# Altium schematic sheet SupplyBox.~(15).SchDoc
size C; SheetNumber: 1; SheetTotal: 1
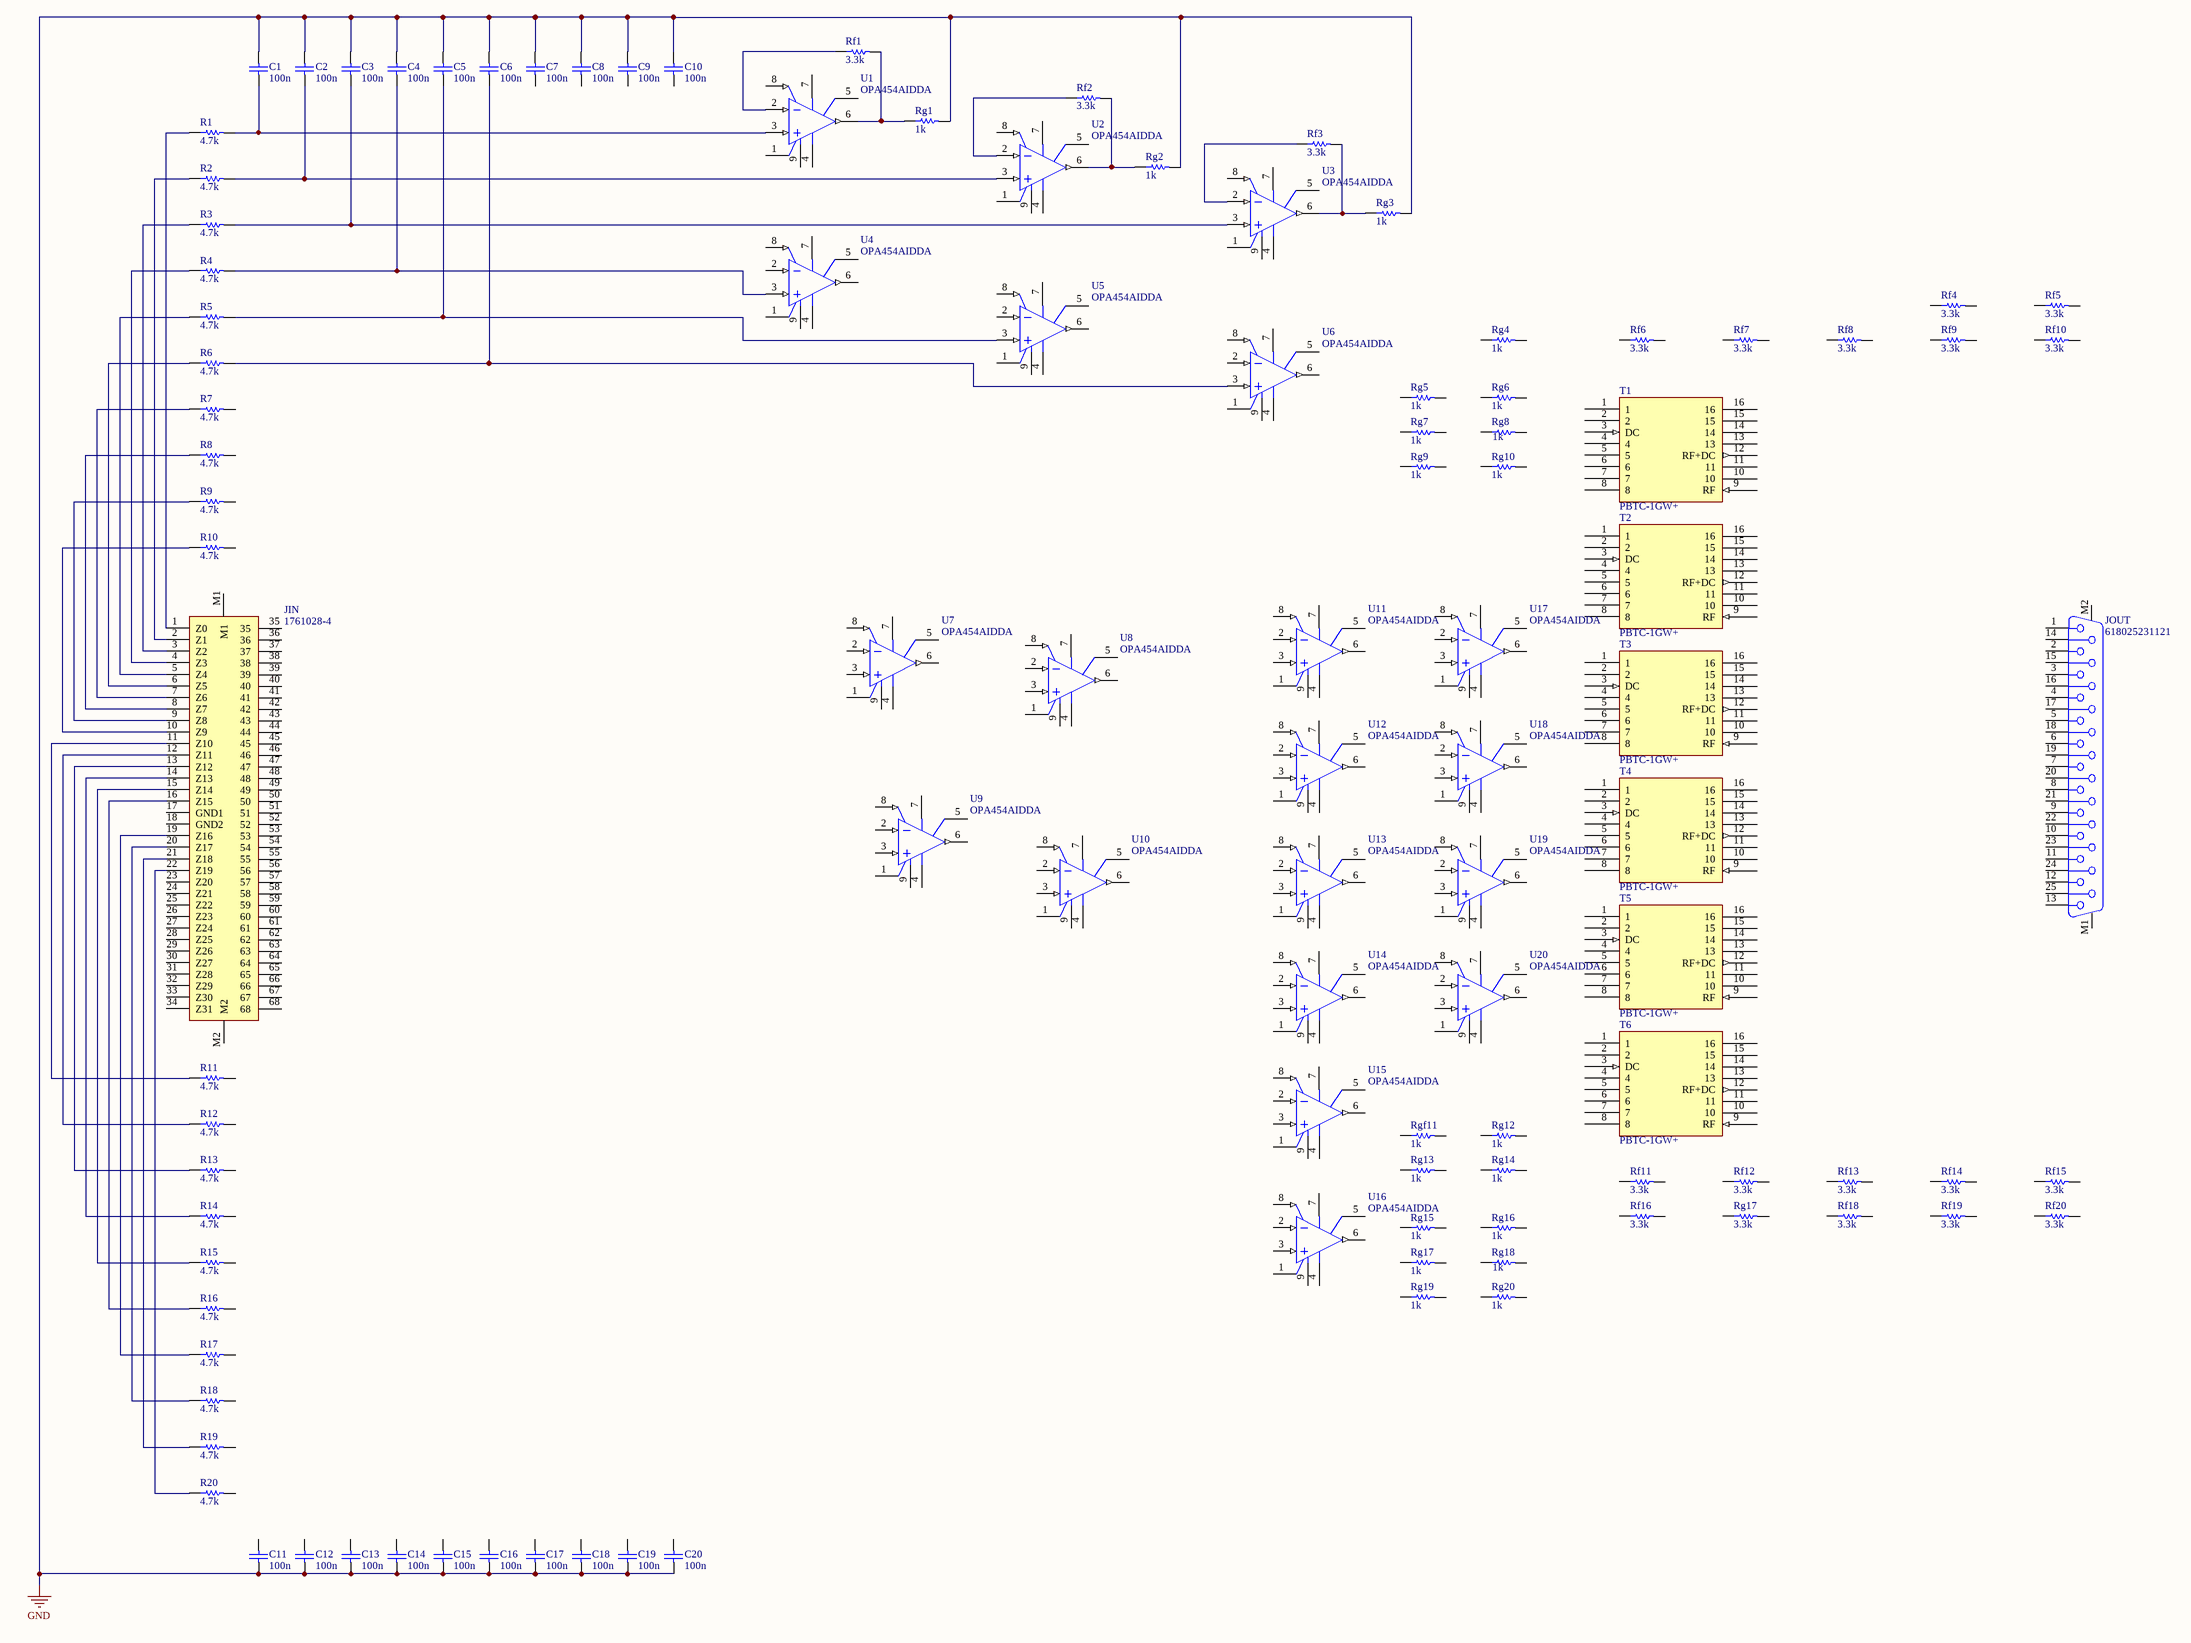
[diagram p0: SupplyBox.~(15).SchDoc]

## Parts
(Parts that share a designator on the sheet are numbered #1, #2 ... from top to bottom, then left to right.)
C1  100n  [CAPC2013X145X48NL20T23]
C2  100n  [CAPC2013X145X48NL20T23]
C3  100n  [CAPC2013X145X48NL20T23]
C4  100n  [CAPC2013X145X48NL20T23]
C5  100n  [CAPC2013X145X48NL20T23]
C6  100n  [CAPC2013X145X48NL20T23]
C7  100n  [CAPC2013X145X48NL20T23]
C8  100n  [CAPC2013X145X48NL20T23]
C9  100n  [CAPC2013X145X48NL20T23]
C10  100n  [CAPC2013X145X48NL20T23]
C11  100n  [CAPC2013X145X48NL20T23]
C12  100n  [CAPC2013X145X48NL20T23]
C13  100n  [CAPC2013X145X48NL20T23]
C14  100n  [CAPC2013X145X48NL20T23]
C15  100n  [CAPC2013X145X48NL20T23]
C16  100n  [CAPC2013X145X48NL20T23]
C17  100n  [CAPC2013X145X48NL20T23]
C18  100n  [CAPC2013X145X48NL20T23]
C19  100n  [CAPC2013X145X48NL20T23]
C20  100n  [CAPC2013X145X48NL20T23]
JIN  1761028-4  [1761028-4-Footprint-1]
JOUT  618025231121  [618025231121]
R1  4.7k  [RESC2013X60X35NL10T20]
R2  4.7k  [RESC2013X60X35NL10T20]
R3  4.7k  [RESC2013X60X35NL10T20]
R4  4.7k  [RESC2013X60X35NL10T20]
R5  4.7k  [RESC2013X60X35NL10T20]
R6  4.7k  [RESC2013X60X35NL10T20]
R7  4.7k  [RESC2013X60X35NL10T20]
R8  4.7k  [RESC2013X60X35NL10T20]
R9  4.7k  [RESC2013X60X35NL10T20]
R10  4.7k  [RESC2013X60X35NL10T20]
R11  4.7k  [RESC2013X60X35NL10T20]
R12  4.7k  [RESC2013X60X35NL10T20]
R13  4.7k  [RESC2013X60X35NL10T20]
R14  4.7k  [RESC2013X60X35NL10T20]
R15  4.7k  [RESC2013X60X35NL10T20]
R16  4.7k  [RESC2013X60X35NL10T20]
R17  4.7k  [RESC2013X60X35NL10T20]
R18  4.7k  [RESC2013X60X35NL10T20]
R19  4.7k  [RESC2013X60X35NL10T20]
R20  4.7k  [RESC2013X60X35NL10T20]
Rf1  3.3k  [RESC2013X60X35ML10T20]
Rf2  3.3k  [RESC2013X60X35ML10T20]
Rf3  3.3k  [RESC2013X60X35ML10T20]
Rf4  3.3k  [RESC2013X60X35ML10T20]
Rf5  3.3k  [RESC2013X60X35ML10T20]
Rf6  3.3k  [RESC2013X60X35ML10T20]
Rf7  3.3k  [RESC2013X60X35ML10T20]
Rf8  3.3k  [RESC2013X60X35ML10T20]
Rf9  3.3k  [RESC2013X60X35ML10T20]
Rf10  3.3k  [RESC2013X60X35ML10T20]
Rf11  3.3k  [RESC2013X60X35ML10T20]
Rf12  3.3k  [RESC2013X60X35ML10T20]
Rf13  3.3k  [RESC2013X60X35ML10T20]
Rf14  3.3k  [RESC2013X60X35ML10T20]
Rf15  3.3k  [RESC2013X60X35ML10T20]
Rf16  3.3k  [RESC2013X60X35ML10T20]
Rf18  3.3k  [RESC2013X60X35ML10T20]
Rf19  3.3k  [RESC2013X60X35ML10T20]
Rf20  3.3k  [RESC2013X60X35ML10T20]
Rg1  1k  [RESC2013X60X35ML10T20]
Rg2  1k  [RESC2013X60X35ML10T20]
Rg3  1k  [RESC2013X60X35ML10T20]
Rg4  1k  [RESC2013X60X35ML10T20]
Rg5  1k  [RESC2013X60X35ML10T20]
Rg6  1k  [RESC2013X60X35ML10T20]
Rg7  1k  [RESC2013X60X35ML10T20]
Rg8  1k  [RESC2013X60X35ML10T20]
Rg9  1k  [RESC2013X60X35ML10T20]
Rg10  1k  [RESC2013X60X35ML10T20]
Rg12  1k  [RESC2013X60X35ML10T20]
Rg13  1k  [RESC2013X60X35ML10T20]
Rg14  1k  [RESC2013X60X35ML10T20]
Rg15  1k  [RESC2013X60X35ML10T20]
Rg16  1k  [RESC2013X60X35ML10T20]
Rg17#1  3.3k  [RESC2013X60X35ML10T20]
Rg17#2  1k  [RESC2013X60X35ML10T20]
Rg18  1k  [RESC2013X60X35ML10T20]
Rg19  1k  [RESC2013X60X35ML10T20]
Rg20  1k  [RESC2013X60X35ML10T20]
Rgf11  1k  [RESC2013X60X35ML10T20]
T1  PBTC-1GW+  [PBTC-1GW+]
T2  PBTC-1GW+  [PBTC-1GW+]
T3  PBTC-1GW+  [PBTC-1GW+]
T4  PBTC-1GW+  [PBTC-1GW+]
T5  PBTC-1GW+  [PBTC-1GW+]
T6  PBTC-1GW+  [PBTC-1GW+]
U1  OPA454AIDDA  [DDA0008C_L]
U2  OPA454AIDDA  [DDA0008C_L]
U3  OPA454AIDDA  [DDA0008C_L]
U4  OPA454AIDDA  [DDA0008C_L]
U5  OPA454AIDDA  [DDA0008C_L]
U6  OPA454AIDDA  [DDA0008C_L]
U7  OPA454AIDDA  [DDA0008C_L]
U8  OPA454AIDDA  [DDA0008C_L]
U9  OPA454AIDDA  [DDA0008C_L]
U10  OPA454AIDDA  [DDA0008C_L]
U11  OPA454AIDDA  [DDA0008C_L]
U12  OPA454AIDDA  [DDA0008C_L]
U13  OPA454AIDDA  [DDA0008C_L]
U14  OPA454AIDDA  [DDA0008C_L]
U15  OPA454AIDDA  [DDA0008C_L]
U16  OPA454AIDDA  [DDA0008C_L]
U17  OPA454AIDDA  [DDA0008C_L]
U18  OPA454AIDDA  [DDA0008C_L]
U19  OPA454AIDDA  [DDA0008C_L]
U20  OPA454AIDDA  [DDA0008C_L]

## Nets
GND: C1.2 C2.2 C3.2 C4.2 C5.2 C6.2 C7.2 C8.2 C9.2 C10.2 C11.1 C12.1 C13.1 C14.1 C15.1 C16.1 C17.1 C18.1 C19.1 C20.1 Rg1.2 Rg2.2 Rg3.2
NetC1_1: C1.1 R1.2 U1.3(IN+)
NetC2_1: C2.1 R2.2 U2.3(IN+)
NetC3_1: C3.1 R3.2 U3.3(IN+)
NetC4_1: C4.1 R4.2 U4.3(IN+)
NetC5_1: C5.1 R5.2 U5.3(IN+)
NetC6_1: C6.1 R6.2 U6.3(IN+)
NetJIN_1: JIN.1(Z0) R1.1
NetJIN_2: JIN.2(Z1) R2.1
NetJIN_3: JIN.3(Z2) R3.1
NetJIN_4: JIN.4(Z3) R4.1
NetJIN_5: JIN.5(Z4) R5.1
NetJIN_6: JIN.6(Z5) R6.1
NetJIN_7: JIN.7(Z6) R7.1
NetJIN_8: JIN.8(Z7) R8.1
NetJIN_9: JIN.9(Z8) R9.1
NetJIN_10: JIN.10(Z9) R10.1
NetJIN_11: JIN.11(Z10) R11.1
NetJIN_12: JIN.12(Z11) R12.1
NetJIN_13: JIN.13(Z12) R13.1
NetJIN_14: JIN.14(Z13) R14.1
NetJIN_15: JIN.15(Z14) R15.1
NetJIN_16: JIN.16(Z15) R16.1
NetJIN_19: JIN.19(Z16) R17.1
NetJIN_20: JIN.20(Z17) R18.1
NetJIN_21: JIN.21(Z18) R19.1
NetJIN_22: JIN.22(Z19) R20.1
NetRf1_1: Rf1.1 U1.2(IN-)
NetRf1_2: Rf1.2 Rg1.1 U1.6(OUT)
NetRf2_1: Rf2.1 U2.2(IN-)
NetRf2_2: Rf2.2 Rg2.1 U2.6(OUT)
NetRf3_1: Rf3.1 U3.2(IN-)
NetRf3_2: Rf3.2 Rg3.1 U3.6(OUT)

Not connected (* = marked no-connect by the designer): C7 1; C8 1; C9 1; C10 1; C11 2; C12 2; C13 2; C14 2; C15 2; C16 2; C17 2; C18 2; C19 2; C20 2; JIN 17(GND1) 18(GND2) 23(Z20) 24(Z21) 25(Z22) 26(Z23) 27(Z24) 28(Z25) 29(Z26) 30(Z27) 31(Z28) 32(Z29) 33(Z30) 34(Z31) 35 36 37 38 39 40 41 42 43 44 45 46 47 48 49 50 51 52 53 54 55 56 57 58 59 60 61 62 63 64 65 66 67 68 M1 M2; JOUT 1 2 3 4 5 6 7 8 9 10 11 12 13 14 15 16 17 18 19 20 21 22 23 24 25 M1 M2; R7 2; R8 2; R9 2; R10 2; R11 2; R12 2; R13 2; R14 2; R15 2; R16 2; R17 2; R18 2; R19 2; R20 2; Rf4 1 2; Rf5 1 2; Rf6 1 2; Rf7 1 2; Rf8 1 2; Rf9 1 2; Rf10 1 2; Rf11 1 2; Rf12 1 2; Rf13 1 2; Rf14 1 2; Rf15 1 2; Rf16 1 2; Rf18 1 2; Rf19 1 2; Rf20 1 2; Rg4 1 2; Rg5 1 2; Rg6 1 2; Rg7 1 2; Rg8 1 2; Rg9 1 2; Rg10 1 2; Rg12 1 2; Rg13 1 2; Rg14 1 2; Rg15 1 2; Rg16 1 2; Rg17#1 1 2; Rg17#2 1 2; Rg18 1 2; Rg19 1 2; Rg20 1 2; Rgf11 1 2; T1 1 2 3(DC) 4 5 6 7 8 9(RF) 10 11 12(RF+DC) 13 14 15 16; T2 1 2 3(DC) 4 5 6 7 8 9(RF) 10 11 12(RF+DC) 13 14 15 16; T3 1 2 3(DC) 4 5 6 7 8 9(RF) 10 11 12(RF+DC) 13 14 15 16; T4 1 2 3(DC) 4 5 6 7 8 9(RF) 10 11 12(RF+DC) 13 14 15 16; T5 1 2 3(DC) 4 5 6 7 8 9(RF) 10 11 12(RF+DC) 13 14 15 16; T6 1 2 3(DC) 4 5 6 7 8 9(RF) 10 11 12(RF+DC) 13 14 15 16; U1 1(E/D_COM) 4(V-) 5(STATUS_FLAG) 7(V+) 8(E/D) 9(EP); U2 1(E/D_COM) 4(V-) 5(STATUS_FLAG) 7(V+) 8(E/D) 9(EP); U3 1(E/D_COM) 4(V-) 5(STATUS_FLAG) 7(V+) 8(E/D) 9(EP); U4 1(E/D_COM) 2(IN-) 4(V-) 5(STATUS_FLAG) 6(OUT) 7(V+) 8(E/D) 9(EP); U5 1(E/D_COM) 2(IN-) 4(V-) 5(STATUS_FLAG) 6(OUT) 7(V+) 8(E/D) 9(EP); U6 1(E/D_COM) 2(IN-) 4(V-) 5(STATUS_FLAG) 6(OUT) 7(V+) 8(E/D) 9(EP); U7 1(E/D_COM) 2(IN-) 3(IN+) 4(V-) 5(STATUS_FLAG) 6(OUT) 7(V+) 8(E/D) 9(EP); U8 1(E/D_COM) 2(IN-) 3(IN+) 4(V-) 5(STATUS_FLAG) 6(OUT) 7(V+) 8(E/D) 9(EP); U9 1(E/D_COM) 2(IN-) 3(IN+) 4(V-) 5(STATUS_FLAG) 6(OUT) 7(V+) 8(E/D) 9(EP); U10 1(E/D_COM) 2(IN-) 3(IN+) 4(V-) 5(STATUS_FLAG) 6(OUT) 7(V+) 8(E/D) 9(EP); U11 1(E/D_COM) 2(IN-) 3(IN+) 4(V-) 5(STATUS_FLAG) 6(OUT) 7(V+) 8(E/D) 9(EP); U12 1(E/D_COM) 2(IN-) 3(IN+) 4(V-) 5(STATUS_FLAG) 6(OUT) 7(V+) 8(E/D) 9(EP); U13 1(E/D_COM) 2(IN-) 3(IN+) 4(V-) 5(STATUS_FLAG) 6(OUT) 7(V+) 8(E/D) 9(EP); U14 1(E/D_COM) 2(IN-) 3(IN+) 4(V-) 5(STATUS_FLAG) 6(OUT) 7(V+) 8(E/D) 9(EP); U15 1(E/D_COM) 2(IN-) 3(IN+) 4(V-) 5(STATUS_FLAG) 6(OUT) 7(V+) 8(E/D) 9(EP); U16 1(E/D_COM) 2(IN-) 3(IN+) 4(V-) 5(STATUS_FLAG) 6(OUT) 7(V+) 8(E/D) 9(EP); U17 1(E/D_COM) 2(IN-) 3(IN+) 4(V-) 5(STATUS_FLAG) 6(OUT) 7(V+) 8(E/D) 9(EP); U18 1(E/D_COM) 2(IN-) 3(IN+) 4(V-) 5(STATUS_FLAG) 6(OUT) 7(V+) 8(E/D) 9(EP); U19 1(E/D_COM) 2(IN-) 3(IN+) 4(V-) 5(STATUS_FLAG) 6(OUT) 7(V+) 8(E/D) 9(EP); U20 1(E/D_COM) 2(IN-) 3(IN+) 4(V-) 5(STATUS_FLAG) 6(OUT) 7(V+) 8(E/D) 9(EP)

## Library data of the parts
C1-C20 = CMP-2007-03167-1: Manufacturer: Vitramon; Part Number: VJ0805Y104KNAAT
JIN = CMP-002-00071-1: Telecom and Datacom Connector, 68 Contact(s), Female, Right Angle, Solder Terminal, #2-56, Receptacle
JOUT = CMP-1502-00202-2: NexarPartId: 18818207; Pitch: 2.77mm; Operating Supply Voltage: 125V; Gender: Female; Insulation Resistance: 5GΩ; Contact Resistance: 30mΩ; Current Rating: 3A; Number of Contacts: 25
R1-R20 = CMP-1659-00011-4: Chip Resistor, 47 KOhm, +/- 1%, 0.125 W, -55 to 155 degC, 0805 (2012 Metric), RoHS, Tape and Reel; Manufacturer: Yageo; Voltage Rating: 150 V
Rf1-Rf16 Rf18-Rf20 Rg17#1 = CMP-1013-00567-2: Chip Resistor, 3.3 KOhm, +/- 1%, 0.125 W, -55 to 155 degC, 0805 (2012 Metric), RoHS, Tape and Reel; Manufacturer: Yageo; Voltage Rating: 150V; Max Power Dissipation: 125mW; Temperature Coefficient: 100ppm/degreesC
Rg1-Rg10 Rg12-Rg16 Rg17#2 Rg18-Rg20 Rgf11 = CMP-2100-03671-1: Chip Resistor, 1 KOhm, +/- 1%, 125 mW, -55 to 155 degC, 0805 (2012 Metric), RoHS, Tape and Reel; Manufacturer: Yageo; Temperature Coefficient: 100ppm/degreesC; Voltage Rating (DC): 150V; Max Power Dissipation: 125mW; Resistance: 1KOhm
T1-T6 = CMP-00025-00003-1: Monitor TEE DC Block, 0.1MHz Min, 1000MHz Max, 1dB Insertion Loss-Max
U1-U20 = CMP-0017-00714-2: High Voltage (100V), High-Current (50mA) Operational Amplifier, G=1 Stable, 10 to 100 V, -55 to 125 degC, 8-pin SOP (DDA8), Green (RoHS & no Sb/Br); Manufacturer: Texas Instruments; Number of Channels: 1; CMRR(Min)(dB): 100; Rating: Catalog; Total Supply Voltage(Min)(+5V is 5, +/-5V is 10): 10; Offset Drift(Typ)(uV/C): 1.6; Vn at 1kHz(Typ)(nV/rtHz): 47; Slew Rate(Typ)(V/us): 13; Sub Family: General Purpose Amplifier, High Output Current Amplifier (>=50mA), High Supply Voltage Amplifier (>=30V), Precision Amplifier; Iq per channel(Max)(mA): 4; GBW(Typ)(MHz): 2.5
